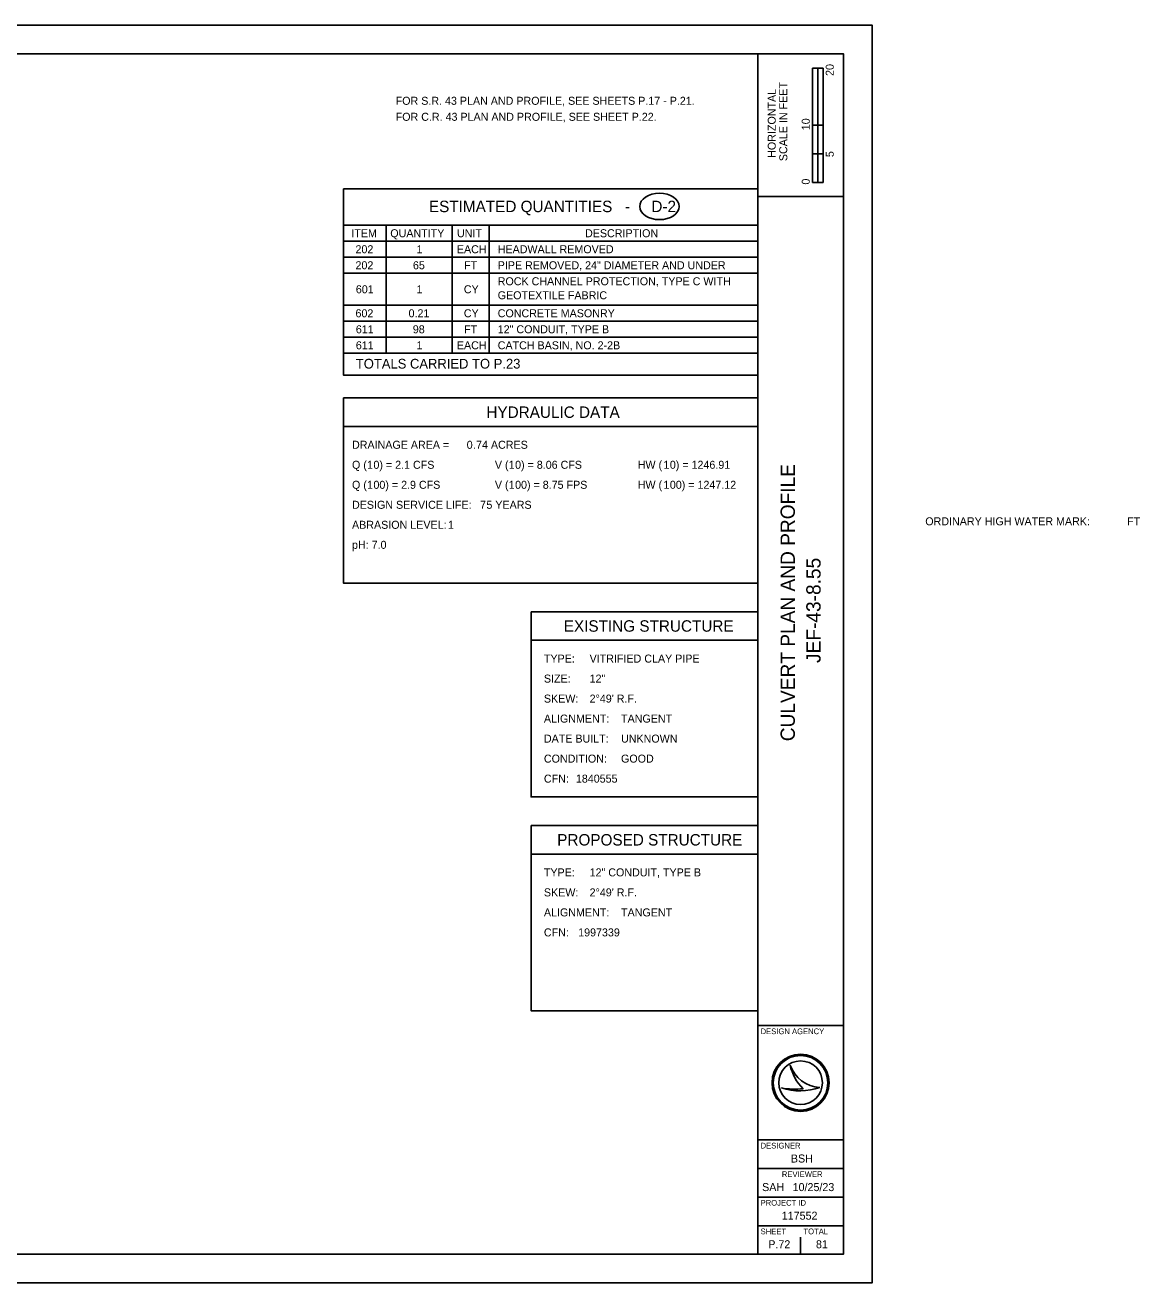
# Model space of a CAD drawing. Extents: x -0.3 to 38.7, y 0 to 22.
# Drawn here: x 19.18 to 38.69, y 0 to 22 of the extents above; entities that cross this region are included whole.
import ezdxf

# ---------------------------------------------------------------- set-up
doc = ezdxf.new("R2010")
doc.units = 0
for name, color, linetype in [('DV_X_Property_Line', 7, 'Continuous'), ('RW_P_Esmt_SH', 7, 'Continuous'), ('RW_P_Esmt_TMP', 7, 'Continuous'), ('SV_P_Control_Cells_Set', 7, 'Continuous')]:
    doc.layers.add(name, color=color, linetype=linetype)

msp = doc.modelspace()

# ---------------------------------------------------------------- linework, layer by layer
at = {"layer": 'DV_X_Property_Line'}
msp.add_ellipse((30.28, 18.829), major_axis=(0.346, 0), ratio=0.666667, dxfattribs=at)
at = {"layer": 'RW_P_Esmt_SH'}
for p, q in [((32.957, 19.25), (32.957, 21.25)), ((33.144, 21.25), (32.957, 21.25)), ((32.957, 20.25), (32.957, 21.25)), ((32.957, 21.25), (33.05, 21.25)), ((33.05, 21.25), (33.051, 21.25)), ((33.051, 21.25), (33.051, 20.25)), ((33.144, 21.25), (33.144, 19.25)), ((33.051, 20.25), (32.957, 20.25)), ((33.143, 20.25), (33.05, 20.25)), ((33.05, 20.25), (33.05, 19.75)), ((33.143, 19.75), (33.143, 20.25)), ((33.05, 19.75), (32.957, 19.75)), ((32.957, 19.75), (32.957, 19.25)), ((33.05, 19.25), (33.05, 19.75)), ((33.05, 19.75), (33.143, 19.75)), ((33.144, 19.25), (32.957, 19.25)), ((32.957, 19.25), (33.05, 19.25)), ((32, 18.5), (24.75, 18.5)), ((25.5, 16.26), (25.5, 18.5)), ((26.65, 16.26), (26.65, 18.5)), ((27.3, 16.26), (27.3, 18.5)), ((32, 18.22), (24.75, 18.22)), ((25.125, 18.08), (25.125, 18.08)), ((26.075, 18.08), (26.075, 18.08)), ((26.975, 18.08), (26.975, 18.08)), ((27.45, 18.08), (27.45, 18.08)), ((32, 17.94), (24.75, 17.94)), ((32, 17.66), (24.75, 17.66)), ((25.125, 17.8), (25.125, 17.8)), ((26.075, 17.8), (26.075, 17.8)), ((26.975, 17.8), (26.975, 17.8)), ((27.45, 17.8), (27.45, 17.8)), ((27.45, 17.52), (27.45, 17.52)), ((32, 17.1), (24.75, 17.1)), ((25.125, 16.96), (25.125, 16.96)), ((26.075, 16.96), (26.075, 16.96)), ((26.975, 16.96), (26.975, 16.96)), ((27.45, 16.96), (27.45, 16.96)), ((32, 16.82), (24.75, 16.82)), ((32, 16.54), (24.75, 16.54)), ((25.125, 16.68), (25.125, 16.68)), ((26.075, 16.68), (26.075, 16.68)), ((26.975, 16.68), (26.975, 16.68)), ((27.45, 16.68), (27.45, 16.68)), ((25.125, 16.4), (25.125, 16.4)), ((26.075, 16.4), (26.075, 16.4)), ((26.975, 16.4), (26.975, 16.4)), ((27.45, 16.4), (27.45, 16.4)), ((32, 16.26), (24.75, 16.26)), ((27.45, 16.12), (27.45, 16.12)), ((32, 14.98), (24.75, 14.98)), ((32, 11.24), (28.034, 11.24)), ((32, 7.5), (28.034, 7.5)), ((32.567, 3.81), (32.567, 3.81)), ((32.417, 3.41), (32.417, 3.41)), ((32.75, 3.5), (32.75, 3.5)), ((33.087, 3.419), (33.087, 3.419)), ((32.375, 0.675), (32.375, 0.675)), ((32.75, 0.5), (32.75, 0.8))]:
    msp.add_line(p, q, dxfattribs=at)
for points in [[(24.75, 19.137), (32, 19.137), (32, 15.88), (24.75, 15.88)], [(24.75, 15.48), (32, 15.48), (32, 12.24), (24.75, 12.24)], [(28.034, 11.74), (32, 11.74), (32, 8.5), (28.034, 8.5)], [(28.034, 8), (32, 8), (32, 4.76), (28.034, 4.76)]]:
    msp.add_lwpolyline(points, close=True, dxfattribs=at)
for radius in [0.5, 0.477, 0.477, 0.382]:
    msp.add_circle((32.75, 3.5), radius, dxfattribs=at)
for centre, radius, start, end in [((33.116, 3.998), 0.58, 198.9257, 198.9319), ((33.347, 3.97), 0.796, 191.6379, 191.6421), ((33.116, 3.998), 0.58, 198.9319, 267.1657), ((33.347, 3.97), 0.796, 191.6421, 226.0947), ((32.739, 4.37), 1.013, 251.4576, 290.0832), ((32.648, 4.654), 1.266, 259.4964, 259.4995), ((32.739, 4.37), 1.013, 251.4527, 251.4576), ((32.648, 4.654), 1.266, 259.4995, 276.6672)]:
    msp.add_arc(centre, radius, start, end, dxfattribs=at)
at = {"layer": 'RW_P_Esmt_TMP'}
for p, q in [((32, 0.5), (32, 21.5)), ((32, 19), (33.5, 19)), ((32, 4.5), (33.5, 4.5)), ((32, 2.5), (33.5, 2.5)), ((32, 2), (33.5, 2)), ((32, 1.5), (33.5, 1.5)), ((32, 1), (33.5, 1))]:
    msp.add_line(p, q, dxfattribs=at)
msp.add_lwpolyline([(1.5, 21.5), (33.5, 21.5), (33.5, 0.5), (1.5, 0.5)], close=True, dxfattribs=at)
at = {"layer": 'SV_P_Control_Cells_Set'}
msp.add_lwpolyline([(0, 0), (34, 0), (34, 22), (0, 22)], close=True, dxfattribs=at)

# ---------------------------------------------------------------- texts
at = {"layer": 'DV_X_Property_Line'}
for s, p in [('FOR S.R. 43 PLAN AND PROFILE, SEE SHEETS P.17 - P.21.', (25.664, 20.607)), ('FOR C.R. 43 PLAN AND PROFILE, SEE SHEET P.22.', (25.664, 20.327))]:
    msp.add_text(s, height=0.14, dxfattribs=at).set_placement(p)
at = {"layer": 'RW_P_Esmt_SH'}
for s, height, p in [('20', 0.14, (33.33, 21.112)), ('SCALE IN FEET', 0.14, (32.517, 19.621)), ('HORIZONTAL', 0.14, (32.315, 19.679)), ('10', 0.14, (32.91, 20.162)), ('5', 0.14, (33.33, 19.691)), ('0', 0.14, (32.91, 19.211)), ('CULVERT PLAN AND PROFILE', 0.25, (32.65, 9.474)), ('JEF-43-8.55', 0.25, (33.1, 10.843))]:
    msp.add_text(s, height=height, rotation=90, dxfattribs=at).set_placement(p)
for s, height, p in [('ESTIMATED QUANTITIES   -     D-2', 0.2, (26.246, 18.729)), ('ITEM', 0.14, (24.888, 18.29)), ('QUANTITY', 0.14, (25.57, 18.29)), ('UNIT', 0.14, (26.737, 18.29)), ('DESCRIPTION', 0.14, (28.978, 18.29)), ('202', 0.14, (24.961, 18.01)), ('1', 0.14, (26.029, 18.01)), ('EACH', 0.14, (26.735, 18.01)), ('HEADWALL REMOVED', 0.14, (27.45, 18.01)), ('202', 0.14, (24.961, 17.73)), ('65', 0.14, (25.966, 17.73)), ('FT', 0.14, (26.863, 17.73)), ('PIPE REMOVED, 24" DIAMETER AND UNDER', 0.14, (27.45, 17.73)), ('601', 0.14, (24.967, 17.31)), ('1', 0.14, (26.029, 17.31)), ('CY', 0.14, (26.857, 17.31)), ('ROCK CHANNEL PROTECTION, TYPE C WITH ', 0.14, (27.45, 17.45)), ('GEOTEXTILE FABRIC', 0.14, (27.45, 17.205)), ('602', 0.14, (24.961, 16.89)), ('0.21', 0.14, (25.89, 16.89)), ('CY', 0.14, (26.857, 16.89)), ('CONCRETE MASONRY', 0.14, (27.45, 16.89)), ('611', 0.14, (24.967, 16.61)), ('98', 0.14, (25.964, 16.61)), ('FT', 0.14, (26.863, 16.61)), ('12" CONDUIT, TYPE B', 0.14, (27.45, 16.61)), ('611', 0.14, (24.967, 16.33)), ('1', 0.14, (26.029, 16.33)), ('EACH', 0.14, (26.735, 16.33)), ('CATCH BASIN, NO. 2-2B', 0.14, (27.45, 16.33)), ('TOTALS CARRIED TO P.23', 0.17, (24.967, 15.993)), ('HYDRAULIC DATA', 0.2, (27.252, 15.13)), ('DRAINAGE AREA =', 0.14, (24.9, 14.59)), ('0', 0.14, (26.907, 14.59)), ('.74 ACRES', 0.14, (27.019, 14.59)), ('Q (', 0.14, (24.9, 14.24)), ('1', 0.14, (25.163, 14.24)), ('0) = 2.1 CFS', 0.14, (25.275, 14.24)), ('V (', 0.14, (27.4, 14.24)), ('1', 0.14, (27.642, 14.24)), ('0) = 8.06 CFS', 0.14, (27.754, 14.24)), ('HW (', 0.14, (29.9, 14.24)), ('1', 0.14, (30.35, 14.24)), ('0) = 1246.91', 0.14, (30.462, 14.24)), ('Q (', 0.14, (24.9, 13.89)), ('1', 0.14, (25.163, 13.89)), ('00) = 2.9 CFS', 0.14, (25.275, 13.89)), ('V (', 0.14, (27.4, 13.89)), ('1', 0.14, (27.642, 13.89)), ('00) = 8.75 FPS', 0.14, (27.754, 13.89)), ('HW (', 0.14, (29.9, 13.89)), ('1', 0.14, (30.35, 13.89)), ('00) = 1247.12', 0.14, (30.462, 13.89)), ('DESIGN SERVICE LIFE:', 0.14, (24.9, 13.54)), ('7', 0.14, (27.14, 13.54)), ('5 YEARS', 0.14, (27.252, 13.54)), ('ABRASION LEVEL:', 0.14, (24.9, 13.19)), ('1', 0.14, (26.58, 13.19)), ('ORDINARY HIGH WATER MARK:', 0.14, (34.932, 13.251)), (' FT', 0.14, (38.411, 13.251)), ('pH: 7.0', 0.14, (24.9, 12.84)), ('EXISTING STRUCTURE', 0.2, (28.606, 11.39)), ('TYPE:', 0.14, (28.258, 10.85)), ('VITRIFIED CLAY PIPE', 0.14, (29.058, 10.85)), ('SIZE:', 0.14, (28.258, 10.5)), ('12"', 0.14, (29.058, 10.5)), ('SKEW:', 0.14, (28.258, 10.15)), ("2°49' R.F.", 0.14, (29.058, 10.15)), ('ALIGNMENT:', 0.14, (28.258, 9.8)), ('TANGENT', 0.14, (29.608, 9.8)), ('DATE BUILT:', 0.14, (28.258, 9.45)), ('UNKNOWN', 0.14, (29.608, 9.45)), ('CONDITION:', 0.14, (28.258, 9.1)), ('GOOD', 0.14, (29.608, 9.1)), ('CFN:', 0.14, (28.258, 8.75)), ('1840555', 0.14, (28.818, 8.75)), ('PROPOSED STRUCTURE', 0.2, (28.491, 7.65)), ('TYPE:', 0.14, (28.258, 7.11)), ('12" CONDUIT, TYPE B', 0.14, (29.058, 7.11)), ('SKEW:', 0.14, (28.258, 6.76)), ("2°49' R.F.", 0.14, (29.058, 6.76)), ('ALIGNMENT:', 0.14, (28.258, 6.41)), ('TANGENT', 0.14, (29.608, 6.41)), ('CFN:', 0.14, (28.258, 6.06)), ('1997339', 0.14, (28.858, 6.06)), ('DESIGN AGENCY', 0.1, (32.05, 4.35)), ('DESIGNER', 0.1, (32.05, 2.35)), ('BSH', 0.14, (32.58, 2.105)), ('REVIEWER', 0.1, (32.422, 1.85)), ('SAH', 0.14, (32.077, 1.605)), ('10/25/23', 0.14, (32.611, 1.605)), ('PROJECT ID', 0.1, (32.05, 1.35)), ('117552', 0.14, (32.421, 1.105)), ('SHEET', 0.1, (32.05, 0.85)), ('TOTAL', 0.1, (32.8, 0.85)), ('P.72', 0.14, (32.185, 0.605)), ('81', 0.14, (33.019, 0.605))]:
    msp.add_text(s, height=height, dxfattribs=at).set_placement(p)

doc.saveas('drawing.dxf')
